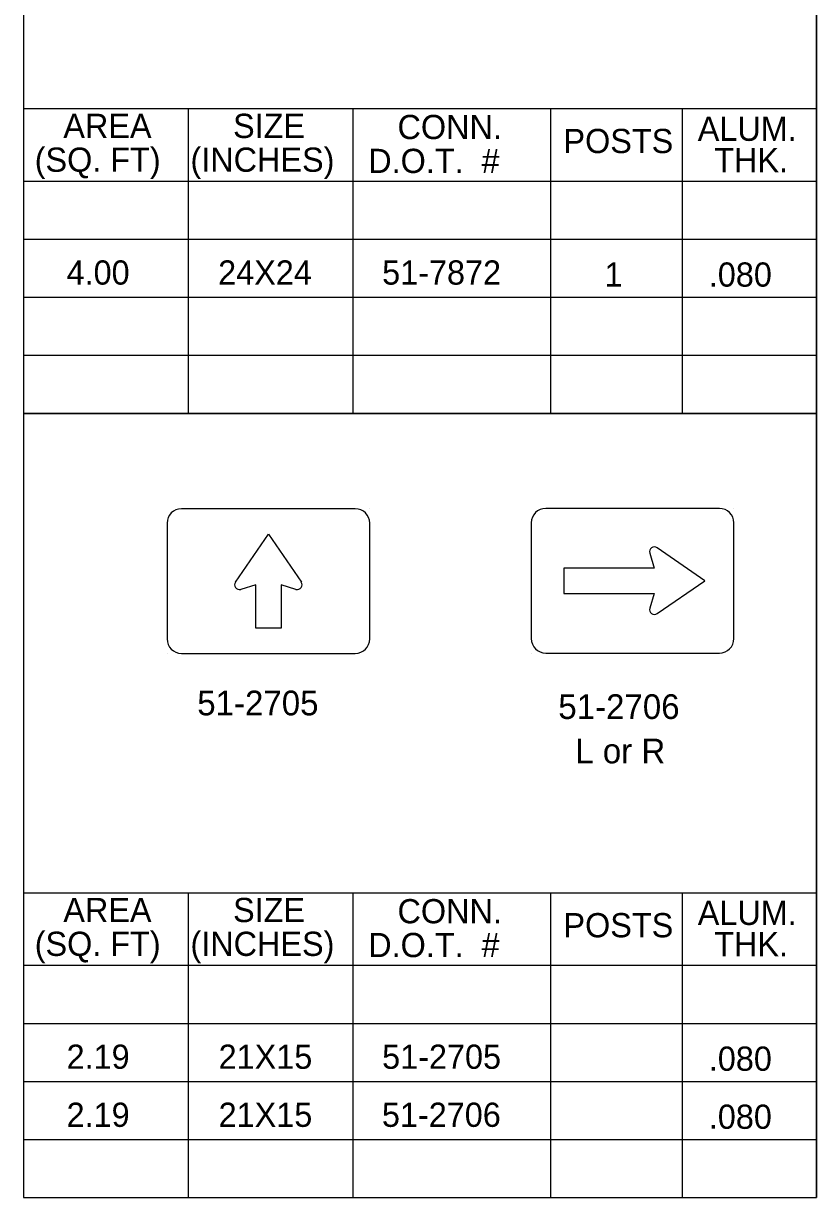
# Model space of a CAD drawing. Extents: x 0 to 2011, y -22 to 1183.
# Drawn here: x 843 to 947.8, y 496.8 to 652 of the extents above; entities that cross this region are included whole.
import ezdxf

# ---------------------------------------------------------------- set-up
doc = ezdxf.new("R2010")
doc.units = 0
for name, color, linetype in [('Level 1', 7, 'Continuous'), ('Level 2', 7, 'Continuous'), ('Level 5', 7, 'Continuous')]:
    doc.layers.add(name, color=color, linetype=linetype)

msp = doc.modelspace()

# ---------------------------------------------------------------- linework, layer by layer
at = {"layer": 'Level 1'}
for p, q in [((886.86, 587.83), (863.91, 587.83)), ((934.96, 587.88), (912.02, 587.88)), ((862, 585.92), (862, 570.62)), ((888.77, 570.62), (888.77, 585.92)), ((910.11, 585.97), (910.11, 570.67)), ((936.88, 570.67), (936.88, 585.97)), ((871.04, 578.15), (875.39, 584.48)), ((875.39, 584.48), (875.39, 584.48)), ((875.39, 584.48), (875.39, 584.48)), ((875.39, 584.48), (879.74, 578.15)), ((925.75, 581.96), (926.34, 579.99)), ((933.05, 578.32), (926.72, 582.67)), ((926.34, 579.99), (914.41, 579.99)), ((914.41, 579.99), (914.41, 576.65)), ((873.72, 577.77), (871.75, 577.18)), ((873.72, 572.05), (873.72, 577.77)), ((879.03, 577.18), (877.06, 577.77)), ((877.06, 577.77), (877.06, 572.05)), ((926.72, 573.97), (933.05, 578.32)), ((933.05, 578.32), (933.05, 578.32)), ((933.05, 578.32), (933.05, 578.32)), ((914.41, 576.65), (926.34, 576.65)), ((926.34, 576.65), (925.75, 574.68)), ((877.06, 572.05), (873.72, 572.05)), ((863.91, 568.71), (886.86, 568.71)), ((912.02, 568.76), (934.96, 568.76))]:
    msp.add_line(p, q, dxfattribs=at)
for centre, radius, start, end in [((863.91, 585.92), 1.91, 90, 180), ((886.86, 585.92), 1.91, 0, 90), ((912.02, 585.97), 1.91, 90, 180), ((934.96, 585.97), 1.91, 0, 90), ((926.36, 582.15), 0.637, 55.5114, 196.6409), ((871.56, 577.79), 0.637, 145.5114, 286.6409), ((879.21, 577.79), 0.637, 253.3591, 34.4886), ((926.36, 574.5), 0.637, 163.3591, 304.4886), ((863.91, 570.62), 1.91, 180, 270), ((886.86, 570.62), 1.91, 270, 360), ((912.02, 570.67), 1.91, 180, 270), ((934.96, 570.67), 1.91, 270, 360)]:
    msp.add_arc(centre, radius, start, end, dxfattribs=at)
at = {"layer": 'Level 2'}
for p, q in [((843.04, 640.71), (947.79, 640.71)), ((864.79, 640.71), (864.79, 600.44)), ((886.54, 640.71), (886.54, 600.44)), ((912.64, 640.71), (912.64, 600.44)), ((930.04, 640.71), (930.04, 600.44)), ((843.04, 631.12), (947.79, 631.12)), ((843.04, 623.45), (947.79, 623.45)), ((843.04, 615.78), (947.79, 615.78)), ((843.04, 608.11), (947.79, 608.11)), ((888.77, 587.83), (888.77, 587.83)), ((936.88, 587.88), (936.88, 587.88)), ((875.39, 572.05), (875.39, 572.05)), ((862, 568.71), (862, 568.71)), ((910.11, 568.76), (910.11, 568.76)), ((843.04, 537.09), (947.79, 537.09)), ((864.79, 537.09), (864.79, 496.81)), ((886.54, 537.09), (886.54, 496.81)), ((912.64, 537.09), (912.64, 496.81)), ((930.04, 537.09), (930.04, 496.81)), ((843.04, 527.5), (947.79, 527.5)), ((843.04, 519.83), (947.79, 519.83)), ((843.04, 512.16), (947.79, 512.16)), ((843.04, 504.48), (947.79, 504.48))]:
    msp.add_line(p, q, dxfattribs=at)
for points in [[(947.79, 704.06), (843.04, 704.06), (843.04, 600.44), (947.79, 600.44)], [(947.79, 600.44), (843.04, 600.44), (843.04, 496.81), (947.79, 496.81)]]:
    msp.add_lwpolyline(points, close=True, dxfattribs=at)
msp.add_lwpolyline([(877.02, 572.05), (877.06, 572.09)], dxfattribs=at)
at = {"layer": 'Level 5'}
for p, q in [((843.04, 830), (843.04, 600.44)), ((843.04, 830), (843.04, 496.81)), ((947.79, 830), (947.79, 496.81))]:
    msp.add_line(p, q, dxfattribs=at)

# ---------------------------------------------------------------- texts
at = {"layer": 'Level 2'}
for s, height, p in [('AREA', 3.2, (848.3, 636.83)), ('SIZE', 3.2, (870.72, 636.83)), ('CONN.', 3.2, (892.44, 636.68)), ('ALUM.', 3.2, (932.1, 636.45)), ('POSTS', 3.2, (914.36, 634.83)), ('(SQ. FT)', 3.2, (844.52, 632.36)), ('(INCHES)', 3.2, (865.09, 632.36)), ('D.O.T.  #', 3.2, (888.57, 632.2)), ('THK.', 3.2, (934.28, 632.31)), ('51-2705', 3.264, (865.99, 560.53)), ('51-2706', 3.264, (913.68, 560.05)), ('L or R', 3.264, (915.92, 554.19)), ('AREA', 3.2, (848.3, 533.21)), ('SIZE', 3.2, (870.72, 533.21)), ('CONN.', 3.2, (892.44, 533.05)), ('ALUM.', 3.2, (932.1, 532.83)), ('POSTS', 3.2, (914.36, 531.2)), ('(SQ. FT)', 3.2, (844.52, 528.74)), ('(INCHES)', 3.2, (865.09, 528.74)), ('D.O.T.  #', 3.2, (888.57, 528.58)), ('THK.', 3.2, (934.28, 528.69))]:
    msp.add_text(s, height=height, dxfattribs=at).set_placement(p)
at = {"layer": 'Level 5'}
for s, p in [(' 4.00', (847.54, 617.45)), ('24X24', (868.75, 617.45)), ('51-7872', (890.41, 617.45)), ('1', (919.77, 617.18)), ('.080', (933.56, 617.18)), (' 2.19', (847.54, 513.82)), ('21X15', (868.81, 513.82)), ('51-2705', (890.41, 513.82)), ('.080', (933.56, 513.56)), (' 2.19', (847.54, 506.15)), ('21X15', (868.81, 506.15)), ('51-2706', (890.38, 506.15)), ('.080', (933.56, 505.89))]:
    msp.add_text(s, height=3.2, dxfattribs=at).set_placement(p)

doc.saveas('drawing.dxf')
